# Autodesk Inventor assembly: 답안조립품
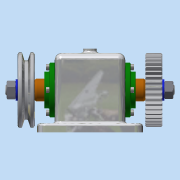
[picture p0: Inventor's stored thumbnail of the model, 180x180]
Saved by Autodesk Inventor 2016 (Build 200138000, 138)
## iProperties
Created: 2018-11
Part Number: 답안조립품
Material: 일반
Document SubType Name: Assembly
Designer: 605-11
Author: 605-11
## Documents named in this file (13)
- C:\Users\605-11\Desktop\481108V1013\답안조립품.iam
- C:\Users\605-11\Desktop\481108V1013\V벨트풀리.ipt
- C:\Users\605-11\Desktop\481108V1013\너트 M12x1.25.ipt
- C:\Users\605-11\Desktop\481108V1013\베어링 6203.ipt
- C:\Users\605-11\Desktop\481108V1013\본체.ipt
- C:\Users\605-11\Desktop\481108V1013\볼트 M4.ipt
- C:\Users\605-11\Desktop\481108V1013\부시.ipt
- C:\Users\605-11\Desktop\481108V1013\스퍼기어.ipt
- C:\Users\605-11\Desktop\481108V1013\오일 실 26 38 8.ipt
- C:\Users\605-11\Desktop\481108V1013\와셔 12x24.ipt
- C:\Users\605-11\Desktop\481108V1013\축.ipt
- C:\Users\605-11\Desktop\481108V1013\커버.ipt
- C:\Users\605-11\Desktop\481108V1013\키 5x5x12.ipt
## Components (1 placed, 1 different names)
1. V벨트풀리:1 — 각도:1
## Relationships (1: Angle 1)
- 각도:1 [Angle]: V벨트풀리:1
